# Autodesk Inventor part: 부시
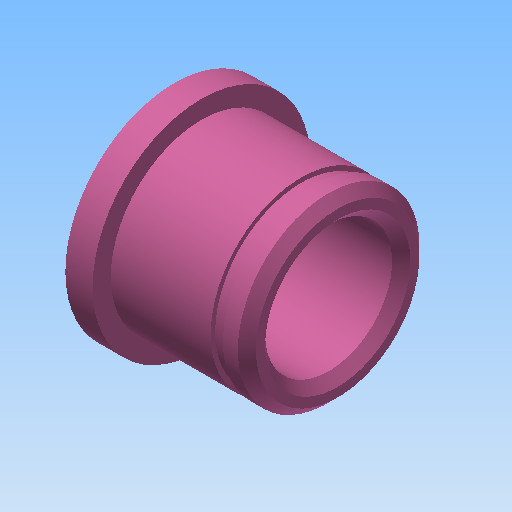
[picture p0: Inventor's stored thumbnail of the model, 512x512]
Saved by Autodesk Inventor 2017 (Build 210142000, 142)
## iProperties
Created: 2019-01
Part Number: 부시
Material: 강철, 연강
Document SubType Name: Modeling
Designer: mduedu
Density: 7.86 g/cm^3
Mass: 25.1828 g
Surface Area: 25.5171 cm^2
Volume: 3.20391 cm^3
Appearance: 분홍색
Author: mduedu
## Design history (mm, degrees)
sketch "스케치1"
  geometry: L1 (0, 0)-(3, 0); L2 (3, 0)-(3, 12); L3 (3, 12)-(0, 12); L4 (0, 12)-(0, 0); L5 (3, 0)-(18, 0); L6 (18, 0)-(18, 10); L7 (18, 10)-(3, 10); L8 (3, 10)-(3, 0)
  constraints: 16 end point, 4 parallel, 2 horizontal, 2 perpendicular
  dimensions: "d0" = 18 distance between parallel lines of L6 L4; "d2" = 3 distance of L2.end L3.end; "d3" = 24 diameter of L3 L1; "d4" = 20 diameter of L7 L5
revolve "회전1" sketch "스케치1" stored, may be unused: angle "d5" = 90 deg
sketch "스케치2"
  geometry: C1 r 7 at (0, 0); 1 further point
  constraints: 1 centre point, 1 coincident
  dimensions: "d6" = 14 diameter of C1
extrude "돌출1" cut sketch "스케치2" stored distance "d7" = 10; taper "d8" = 0 deg
chamfer "모따기1" distance "d9" = 1; stored, may be unused: second distance "d10" = 2, angle "d11" = 45 deg
node "작업 평면1"
sketch "스케치3"
  geometry: C1 r 9.5 at (0, 0); C2 r 10 at (0, 0) reference; 1 further point
  constraints: 1 centre point, 1 coincident
  dimensions: "d13" = 19 diameter of C1
extrude "돌출2" cut sketch "스케치3" distance "d14" = 1.35; taper "d15" = 0 deg
node "솔리드1"
other parameters: "d12" = 11
